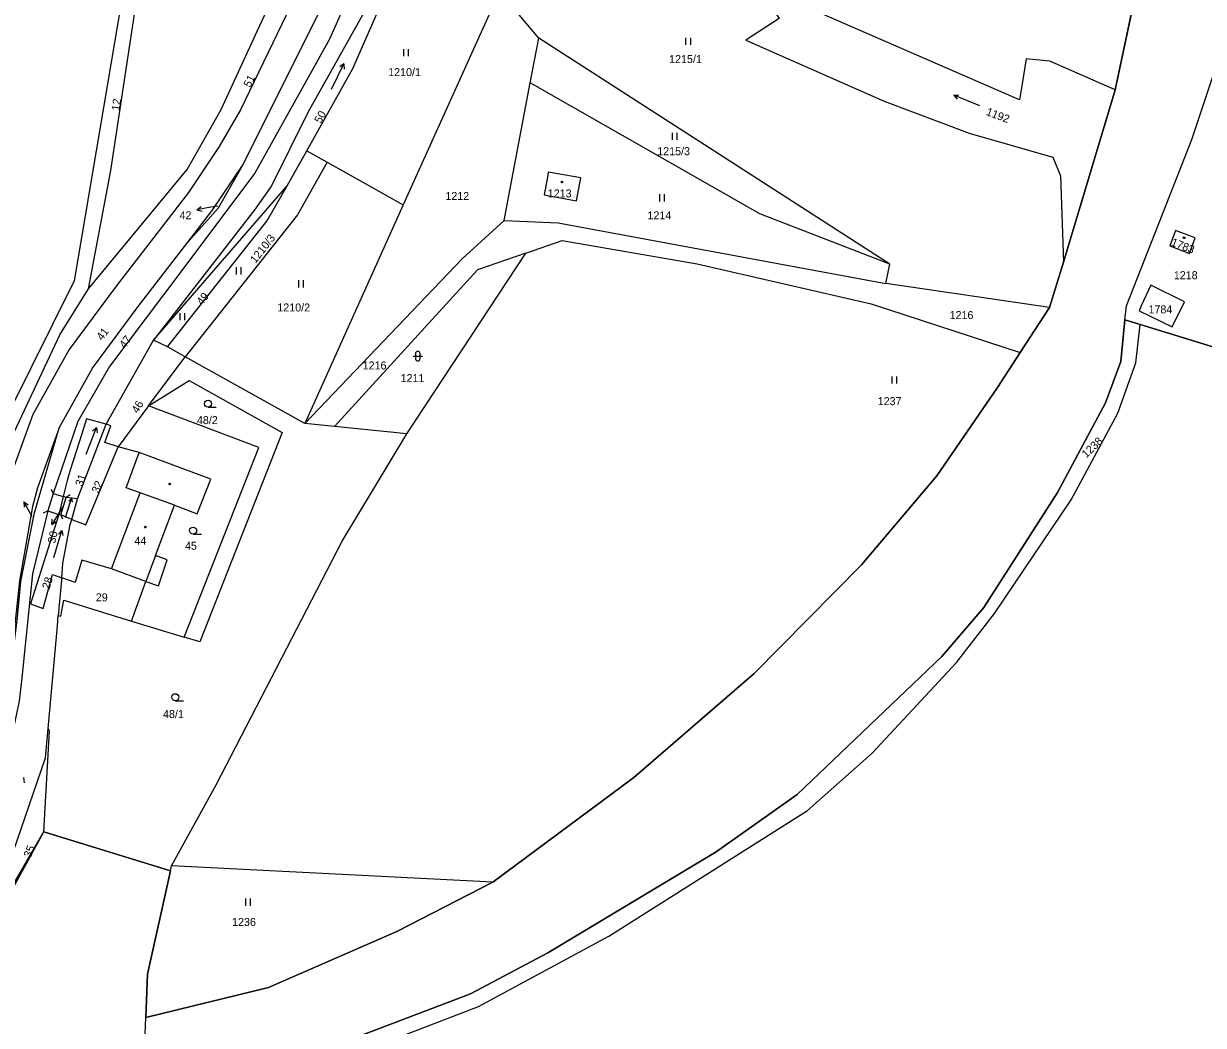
# Model space of a CAD drawing. Extents: x -520431 to -517205, y -1075927 to -1074013.
# Drawn here: x -517864.6 to -517614, y -1074705.2 to -1074492.4 of the extents above; entities that cross this region are included whole.
import ezdxf

# ---------------------------------------------------------------- set-up
doc = ezdxf.new("R2010")
doc.units = 0
for name, color, linetype in [('Hranice parcel', 7, 'Continuous'), ('Parcelní čísla', 7, 'Continuous'), ('Pop  PČ popisy', 7, 'Continuous'), ('Vnitřní kresba', 7, 'Continuous'), ('Vrstva 54', 7, 'Continuous'), ('Značky budov', 7, 'Continuous'), ('Značky kultur', 7, 'Continuous')]:
    doc.layers.add(name, color=color, linetype=linetype)

msp = doc.modelspace()

# ---------------------------------------------------------------- linework, layer by layer
at = {"layer": 'Hranice parcel'}
for p, q in [((-517623.84, -1074464.38), (-517632.78, -1074506.5)), ((-517817.95, -1074522.31), (-517797, -1074480.31)), ((-517763.49, -1074485.49), (-517783.95, -1074530.89)), ((-517755.18, -1074495.54), (-517763.49, -1074485.49)), ((-517756.97, -1074505.02), (-517755.18, -1074495.54)), ((-517680.63, -1074543.54), (-517755.18, -1074495.54)), ((-517762.5, -1074534.25), (-517756.97, -1074505.02)), ((-517632.78, -1074506.5), (-517643.73, -1074543.1)), ((-517808.59, -1074526.9), (-517804.45, -1074519.47)), ((-517804.45, -1074519.47), (-517800.13, -1074521.88)), ((-517800.13, -1074521.88), (-517783.95, -1074530.89)), ((-517824.52, -1074532.15), (-517817.95, -1074522.31)), ((-517836.98, -1074559.66), (-517808.59, -1074526.9)), ((-517783.95, -1074530.89), (-517804.88, -1074577.34)), ((-517829.72, -1074538.87), (-517824.52, -1074532.15)), ((-517840.27, -1074552.5), (-517829.72, -1074538.87)), ((-517783.17, -1074579.57), (-517757.94, -1074541.16)), ((-517681.44, -1074547.61), (-517680.63, -1074543.54)), ((-517643.73, -1074543.1), (-517646.72, -1074552.73)), ((-517646.72, -1074552.73), (-517681.44, -1074547.61)), ((-517646.72, -1074552.73), (-517652.93, -1074562.28)), ((-517630.68, -1074555.36), (-517627.46, -1074556.34)), ((-517847.04, -1074577.48), (-517836.98, -1074559.66)), ((-517834.06, -1074561.05), (-517836.98, -1074559.66)), ((-517830.3, -1074563.19), (-517834.06, -1074561.05)), ((-517838.04, -1074573.61), (-517830.3, -1074563.19)), ((-517804.88, -1074577.34), (-517830.3, -1074563.19)), ((-517838.04, -1074573.61), (-517844.5, -1074582.32)), ((-517853.15, -1074593.36), (-517847.04, -1074577.48)), ((-517798.53, -1074577.99), (-517804.88, -1074577.34)), ((-517783.17, -1074579.57), (-517798.53, -1074577.99)), ((-517858.33, -1074592.23), (-517859.45, -1074595.9)), ((-517856.16, -1074592.89), (-517857.09, -1074596.67)), ((-517855.55, -1074593.08), (-517856.16, -1074592.89)), ((-517853.15, -1074593.36), (-517855.55, -1074593.08)), ((-517854.38, -1074597.76), (-517853.15, -1074593.36)), ((-517836.59, -1074605.44), (-517832.55, -1074594.69)), ((-517856.68, -1074596.8), (-517857.09, -1074596.67)), ((-517854.38, -1074597.76), (-517856.68, -1074596.8)), ((-517856.5, -1074610.12), (-517856.24, -1074607.02)), ((-517838.66, -1074610.94), (-517845.95, -1074608.24)), ((-517841.65, -1074619.39), (-517838.66, -1074610.94)), ((-517841.65, -1074619.39), (-517830.49, -1074622.74)), ((-517859.96, -1074648.38), (-517859.4, -1074642.17)), ((-517872.62, -1074685.25), (-517859.96, -1074648.38)), ((-517871.51, -1074684.58), (-517860.3, -1074664.09)), ((-517833.42, -1074672.42), (-517860.3, -1074664.09)), ((-517838.25, -1074694.34), (-517833.42, -1074672.42)), ((-517833.42, -1074672.42), (-517833.18, -1074671.34)), ((-517764.92, -1074674.8), (-517833.18, -1074671.34)), ((-517838.61, -1074703.56), (-517838.25, -1074694.34))]:
    msp.add_line(p, q, dxfattribs=at)
for points in [[(-517756.55, -1074396.3), (-517774.54, -1074438.04), (-517780.08, -1074451.76), (-517799.59, -1074495.72), (-517815.46, -1074524.18), (-517834.85, -1074550.05), (-517846.38, -1074565.25), (-517853.07, -1074576.92), (-517858.33, -1074592.23)], [(-517767.9, -1074441.76), (-517727.11, -1074460.94), (-517716.1, -1074473.52), (-517704.12, -1074491.36), (-517711.23, -1074495.91), (-517681.81, -1074508.89), (-517663.73, -1074515.66), (-517645.97, -1074520.79), (-517644.4, -1074524.77), (-517643.73, -1074543.1)], [(-517630.68, -1074555.36), (-517630.37, -1074552.39), (-517616.46, -1074517.06), (-517610.81, -1074500.02), (-517605.06, -1074475.2), (-517602.69, -1074475.75), (-517596.08, -1074449.57)], [(-517850.83, -1074548.74), (-517846.09, -1074523.6), (-517837.85, -1074469.32), (-517841.16, -1074453.61)], [(-517779.16, -1074466.54), (-517804.25, -1074511.32), (-517811.94, -1074526.9), (-517815.48, -1074531.89), (-517836.98, -1074559.66)], [(-517804.45, -1074519.47), (-517794.69, -1074501.94), (-517779.16, -1074466.54)], [(-517632.78, -1074506.5), (-517646.61, -1074500.39), (-517651.65, -1074499.91), (-517652.5, -1074505.18), (-517653.05, -1074508.61), (-517699.45, -1074488.45), (-517712.07, -1074468.12)], [(-517804.75, -1074469.93), (-517803.69, -1074472.53), (-517802.55, -1074475.63), (-517802.66, -1074477.22), (-517802.88, -1074478.21), (-517818.5, -1074510.75), (-517823.02, -1074518.54), (-517829.54, -1074528.3), (-517844.96, -1074548.2), (-517854.94, -1074561.68), (-517862.64, -1074575.46), (-517868.09, -1074590.49), (-517871.22, -1074605.22)], [(-517850.83, -1074548.74), (-517829.82, -1074523.39), (-517822.66, -1074510.67), (-517814.93, -1074493.91), (-517807.89, -1074478.79), (-517805.17, -1074471.77), (-517804.75, -1074469.93)], [(-517841.4, -1074473.36), (-517853.85, -1074547.07), (-517867.75, -1074575)], [(-517680.63, -1074543.54), (-517708.25, -1074532.83), (-517756.97, -1074505.02)], [(-517800.13, -1074521.88), (-517806.44, -1074533.02), (-517830.3, -1074563.19)], [(-517829.72, -1074538.87), (-517823.2, -1074531.56), (-517817.95, -1074522.31)], [(-517754.02, -1074528.78), (-517747.14, -1074530.03), (-517746.23, -1074525.16), (-517753.16, -1074523.94), (-517753.27, -1074524.58), (-517754.02, -1074528.78)], [(-517834.06, -1074561.05), (-517812.93, -1074534.37), (-517808.59, -1074526.9)], [(-517804.88, -1074577.34), (-517771.44, -1074542.38), (-517762.5, -1074534.25)], [(-517762.5, -1074534.25), (-517751.09, -1074534.76), (-517681.44, -1074547.61)], [(-517619.93, -1074536.35), (-517621.17, -1074539.65), (-517617, -1074541.25), (-517615.75, -1074537.93), (-517619.93, -1074536.35)], [(-517757.94, -1074541.16), (-517750.21, -1074538.47), (-517721.56, -1074543.48), (-517684.57, -1074551.97), (-517652.93, -1074562.28)], [(-517757.94, -1074541.16), (-517768.16, -1074544.72), (-517798.53, -1074577.99)], [(-517868.75, -1074583.75), (-517856.91, -1074558.52), (-517850.83, -1074548.74)], [(-517627.69, -1074553.42), (-517620.64, -1074556.82), (-517618.05, -1074551.52), (-517625.15, -1074548.01), (-517627.21, -1074552.39), (-517627.69, -1074553.42)], [(-517857, -1074578.27), (-517849.98, -1074565.6), (-517840.27, -1074552.5)], [(-517830.32, -1074762.49), (-517815.05, -1074725.17), (-517810, -1074719.37), (-517796.16, -1074712.07), (-517767.96, -1074701.22), (-517740.26, -1074686.25), (-517698.1, -1074659.55), (-517684.35, -1074647.39), (-517666.49, -1074628.12), (-517658.4, -1074617.73), (-517642.13, -1074593.59), (-517632.17, -1074575.15), (-517628.34, -1074564.49), (-517627.46, -1074556.34)], [(-517808.22, -1074713.87), (-517802.82, -1074711.12), (-517769.64, -1074698.49), (-517753.22, -1074689.81), (-517717.47, -1074668.36), (-517700.27, -1074656.19), (-517669.54, -1074626.83), (-517660.64, -1074616.44), (-517645.03, -1074592.04), (-517634.84, -1074572.98), (-517631.58, -1074564.18), (-517630.68, -1074555.36)], [(-517627.46, -1074556.34), (-517610.15, -1074561.61), (-517598.94, -1074560.06)], [(-517652.93, -1074562.28), (-517657.74, -1074569.69), (-517670.64, -1074588.48), (-517686.63, -1074607.37), (-517709.44, -1074630.49), (-517734.95, -1074652.57), (-517764.92, -1074674.8)], [(-517838.04, -1074573.61), (-517829.46, -1074568.26), (-517809.65, -1074579.26), (-517827.13, -1074623.76), (-517830.49, -1074622.74)], [(-517830.49, -1074622.74), (-517814.65, -1074582.45), (-517838.04, -1074573.61)], [(-517847.04, -1074577.48), (-517851.2, -1074576.4), (-517852.24, -1074579.55), (-517854.68, -1074587.31), (-517855.35, -1074589.5), (-517856.16, -1074592.89)], [(-517873.88, -1074658.35), (-517870.8, -1074649.43), (-517867.48, -1074631.42), (-517865.97, -1074619.23), (-517865.18, -1074610.95), (-517862.25, -1074596.31), (-517859.75, -1074587.55), (-517857, -1074578.27)], [(-517857, -1074578.27), (-517861.63, -1074591.03), (-517862.7, -1074595.01), (-517865.49, -1074610.76), (-517867.65, -1074631.38), (-517872.16, -1074652.95)], [(-517844.5, -1074582.32), (-517847.36, -1074581.43), (-517846.09, -1074577.84), (-517847.04, -1074577.48)], [(-517833.18, -1074671.34), (-517823.67, -1074654.1), (-517796.95, -1074602.33), (-517783.17, -1074579.57)], [(-517854.38, -1074597.76), (-517851.4, -1074598.89), (-517844.5, -1074582.32)], [(-517832.55, -1074594.69), (-517827.71, -1074596.57), (-517824.85, -1074589.21), (-517840.06, -1074583.53), (-517844.5, -1074582.32)], [(-517859.45, -1074595.9), (-517862.7, -1074609.3), (-517864.95, -1074631.41), (-517865.5, -1074636.32), (-517869.72, -1074655.75), (-517875.42, -1074672.76), (-517883.05, -1074691.54)], [(-517857.09, -1074596.67), (-517863.14, -1074615.7), (-517860.41, -1074616.69), (-517858.45, -1074609.42), (-517856.5, -1074610.12)], [(-517856.24, -1074607.02), (-517854.67, -1074598.81), (-517854.38, -1074597.76)], [(-517845.95, -1074608.24), (-517852.22, -1074606.43), (-517853.67, -1074611.13), (-517856.5, -1074610.12)], [(-517838.66, -1074610.94), (-517835.95, -1074611.84), (-517834.08, -1074606.35), (-517836.59, -1074605.44)], [(-517856.5, -1074610.12), (-517856.54, -1074610.63), (-517857.22, -1074618.15)], [(-517857.22, -1074618.15), (-517856.71, -1074618.31), (-517856.06, -1074614.87), (-517841.65, -1074619.39)], [(-517859.4, -1074642.17), (-517857.42, -1074620.35), (-517857.22, -1074618.15)], [(-517860.3, -1074664.09), (-517859.09, -1074642.62), (-517859.4, -1074642.17)], [(-517764.92, -1074674.8), (-517785.33, -1074685.28), (-517812.58, -1074697.2), (-517838.61, -1074703.56)], [(-517839.2, -1074718.99), (-517838.88, -1074710.63), (-517838.61, -1074703.56)]]:
    msp.add_lwpolyline(points, dxfattribs=at)
at = {"layer": 'Pop  PČ popisy'}
for p, q in [((-517827.77, -1074531.95), (-517826.87, -1074531.28)), ((-517824.81, -1074531.43), (-517827.77, -1074531.95)), ((-517827.77, -1074531.95), (-517826.69, -1074532.27)), ((-517823.36, -1074531.18), (-517824.81, -1074531.43)), ((-517863.07, -1074596.64), (-517864.57, -1074594.04)), ((-517864.57, -1074594.04), (-517863.64, -1074594.66)), ((-517864.57, -1074594.04), (-517864.5, -1074595.16)), ((-517862.77, -1074597.19), (-517863.07, -1074596.64)), ((-517857.01, -1074596.25), (-517858.6, -1074598.79)), ((-517856.28, -1074595.1), (-517857.01, -1074596.25)), ((-517858.6, -1074598.79), (-517858.49, -1074597.68)), ((-517858.6, -1074598.79), (-517857.65, -1074598.21))]:
    msp.add_line(p, q, dxfattribs=at)
at = {"layer": 'Vnitřní kresba'}
for p, q in [((-517842.8, -1074591), (-517840.06, -1074583.53)), ((-517858.75, -1074591.32), (-517858.33, -1074592.23)), ((-517858.33, -1074592.23), (-517856.16, -1074592.89)), ((-517845.95, -1074608.24), (-517839.81, -1074592.1)), ((-517839.81, -1074592.1), (-517842.8, -1074591)), ((-517832.55, -1074594.69), (-517839.81, -1074592.1)), ((-517856.68, -1074596.8), (-517855.55, -1074593.08)), ((-517854.73, -1074592.51), (-517855.55, -1074593.08)), ((-517860.33, -1074596.37), (-517859.45, -1074595.9)), ((-517859.45, -1074595.9), (-517857.09, -1074596.67)), ((-517856.24, -1074597.7), (-517856.68, -1074596.8)), ((-517836.59, -1074605.44), (-517838.66, -1074610.94))]:
    msp.add_line(p, q, dxfattribs=at)
at = {"layer": 'Vrstva 54'}
for points in [[(-517872.62, -1074685.25), (-517860.3, -1074664.09), (-517833.42, -1074672.42), (-517838.25, -1074694.34), (-517838.61, -1074703.56), (-517812.58, -1074697.2), (-517785.33, -1074685.28), (-517764.92, -1074674.8), (-517734.95, -1074652.57), (-517709.44, -1074630.49), (-517686.63, -1074607.37), (-517670.64, -1074588.48), (-517657.74, -1074569.69), (-517652.93, -1074562.28), (-517646.72, -1074552.73), (-517643.73, -1074543.1), (-517632.78, -1074506.5), (-517623.84, -1074464.38)], [(-517610.15, -1074561.61), (-517627.46, -1074556.34), (-517630.68, -1074555.36), (-517631.58, -1074564.18), (-517634.84, -1074572.98), (-517645.03, -1074592.04), (-517660.64, -1074616.44), (-517669.54, -1074626.83), (-517700.27, -1074656.19), (-517717.47, -1074668.36), (-517753.22, -1074689.81), (-517769.64, -1074698.49), (-517802.82, -1074711.12)]]:
    msp.add_lwpolyline(points, dxfattribs=at)
at = {"layer": 'Značky budov'}
for centre in [(-517750.24, -1074526.06), (-517618.11, -1074537.91), (-517833.57, -1074590.2), (-517838.75, -1074599.37)]:
    msp.add_circle(centre, 0.175, dxfattribs=at)
at = {"layer": 'Značky kultur'}
for p, q in [((-517723.91, -1074496.91), (-517723.91, -1074495.41)), ((-517722.91, -1074496.91), (-517722.91, -1074495.41)), ((-517783.85, -1074499.33), (-517783.85, -1074497.83)), ((-517782.85, -1074499.33), (-517782.85, -1074497.83)), ((-517799.19, -1074506.35), (-517796.56, -1074500.96)), ((-517796.56, -1074500.96), (-517797.44, -1074501.62)), ((-517796.56, -1074500.96), (-517796.54, -1074502.06)), ((-517667.04, -1074507.63), (-517665.95, -1074507.53)), ((-517661.48, -1074509.88), (-517667.04, -1074507.63)), ((-517667.04, -1074507.63), (-517666.33, -1074508.46)), ((-517726.8, -1074517.1), (-517726.8, -1074515.6)), ((-517725.8, -1074517.1), (-517725.8, -1074515.6)), ((-517729.45, -1074530.18), (-517729.45, -1074528.68)), ((-517728.45, -1074530.18), (-517728.45, -1074528.68)), ((-517819.35, -1074545.68), (-517819.35, -1074544.18)), ((-517818.35, -1074545.68), (-517818.35, -1074544.18)), ((-517806.13, -1074548.45), (-517806.13, -1074546.95)), ((-517805.13, -1074548.45), (-517805.13, -1074546.95)), ((-517831.33, -1074555.44), (-517831.33, -1074553.94)), ((-517830.33, -1074555.44), (-517830.33, -1074553.94)), ((-517781.87, -1074563.06), (-517779.87, -1074563.06)), ((-517781.37, -1074562.56), (-517781.37, -1074563.56)), ((-517780.37, -1074563.56), (-517780.37, -1074562.56)), ((-517680.12, -1074568.87), (-517680.12, -1074567.37)), ((-517679.12, -1074568.87), (-517679.12, -1074567.37)), ((-517825.42, -1074573.9), (-517823.67, -1074573.9)), ((-517851.27, -1074583.85), (-517849.12, -1074578.25)), ((-517849.12, -1074578.25), (-517849.94, -1074578.98)), ((-517849.12, -1074578.25), (-517849, -1074579.34)), ((-517855.67, -1074597.35), (-517854.44, -1074593.33)), ((-517854.44, -1074593.33), (-517854.97, -1074593.88)), ((-517854.44, -1074593.33), (-517854.3, -1074594.09)), ((-517858.19, -1074605.8), (-517856.44, -1074600.07)), ((-517856.44, -1074600.07), (-517857.21, -1074600.85)), ((-517856.44, -1074600.07), (-517856.25, -1074601.15)), ((-517828.59, -1074600.87), (-517826.84, -1074600.87)), ((-517832.38, -1074636.26), (-517830.63, -1074636.26)), ((-517864.64, -1074652.59), (-517864.45, -1074653.67)), ((-517817.4, -1074679.8), (-517817.4, -1074678.3)), ((-517816.4, -1074679.8), (-517816.4, -1074678.3))]:
    msp.add_line(p, q, dxfattribs=at)
for centre in [(-517825.42, -1074573.15), (-517828.59, -1074600.12), (-517832.38, -1074635.51)]:
    msp.add_circle(centre, 0.75, dxfattribs=at)
for centre, start, end in [((-517780.87, -1074562.56), 0, 180), ((-517780.87, -1074563.56), 180, 359.9879)]:
    msp.add_arc(centre, 0.5, start, end, dxfattribs=at)

# ---------------------------------------------------------------- texts
at = {"layer": 'Parcelní čísla'}
for s, p in [('1215/1', (-517727.49, -1074500.79)), ('1210/1', (-517787.16, -1074503.57)), ('1215/3', (-517730.01, -1074520.37)), ('1212', (-517775.01, -1074529.89)), ('1213', (-517753.26, -1074529.34)), ('42', (-517831.47, -1074533.98)), ('1214', (-517732.09, -1074534)), ('1218', (-517620.3, -1074546.71)), ('1210/2', (-517810.7, -1074553.57)), ('1216', (-517667.92, -1074555.18)), ('1784', (-517625.68, -1074553.97)), ('1216', (-517792.58, -1074565.88)), ('1211', (-517784.52, -1074568.57)), ('1237', (-517683.19, -1074573.47)), ('48/2', (-517827.78, -1074577.5)), ('44', (-517841.05, -1074603.12)), ('45', (-517830.31, -1074604.18)), ('29', (-517849.25, -1074615.15)), ('48/1', (-517834.98, -1074639.94)), ('1236', (-517820.31, -1074684.11))]:
    msp.add_text(s, height=1.7, dxfattribs=at).set_placement(p)
for s, rotation, p in [('51', 64, (-517816.46, -1074506.11)), ('12', 82, (-517844.25, -1074511)), ('50', 61, (-517801.48, -1074513.75)), ('1192', 339, (-517660.32, -1074511.77)), ('1210/3', 52, (-517815.32, -1074543.47)), ('1783', 339, (-517621.03, -1074539.51)), ('49', 51, (-517826.7, -1074552.36)), ('41', 53, (-517847.91, -1074559.85)), ('47', 53, (-517843.09, -1074561.52)), ('46', 60, (-517840.31, -1074575.33)), ('1238', 44, (-517638.88, -1074584.8)), ('31', 71, (-517852.11, -1074590.85)), ('32', 68, (-517848.65, -1074592.31)), ('30', 78, (-517857.85, -1074602.91)), ('28', 72, (-517859.12, -1074612.7)), ('35', 68, (-517863.1, -1074669.75))]:
    msp.add_text(s, height=1.7, rotation=rotation, dxfattribs=at).set_placement(p)

doc.saveas('drawing.dxf')
